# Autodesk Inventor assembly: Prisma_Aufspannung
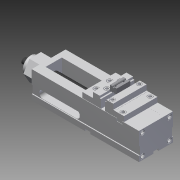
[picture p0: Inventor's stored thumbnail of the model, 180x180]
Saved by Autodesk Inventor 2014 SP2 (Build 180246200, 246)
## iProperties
Created: 2015-06
Part Number: Prisma_Aufspannung
Document SubType Name: Assembly
Designer: e_krauts
Author: e_krauts
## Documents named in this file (4)
- C:\SolidCAM_Temp\PRISMA_AUFSPANNUNG-3\DesignModel.iam
- Z:\VDW-Nachwuchsstiftung Intern\Mitarbeiter Ablage\Steffen Krauth\IVCAM\Prisma mit Passfedernut.ipt
- C:\SolidCAM_Temp\PRISMA_AUFSPANNUNG-3\Schraubstock.iam
- C:\SolidCAM_Temp\PRISMA_AUFSPANNUNG-3\Prisma mit Passfedernut-01.ipt
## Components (3 placed, 2 different names)
1. Prisma mit Passfedernut-01:1 — Passend:1, Passend:2, Fluchtend:1, Passend:3, Passend:4, Passend:5, Fluchtend:2, Passend:6
2. Schraubstock:1 [sub-assembly] — Passend:1, Passend:2, Fluchtend:1, Passend:3
3. Schraubstock:2 [sub-assembly] — Passend:4, Passend:5, Fluchtend:2, Passend:6
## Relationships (8: Mate 6, Flush 2)
- Passend:1 [Mate]: Prisma mit Passfedernut-01:1 ↔ Schraubstock:1
- Passend:2 [Mate]: Prisma mit Passfedernut-01:1 ↔ Schraubstock:1
- Fluchtend:1 [Flush]: Prisma mit Passfedernut-01:1 ↔ Schraubstock:1
- Passend:3 [Mate]: Prisma mit Passfedernut-01:1 ↔ Schraubstock:1
- Passend:4 [Mate]: Prisma mit Passfedernut-01:1 ↔ Schraubstock:2
- Passend:5 [Mate]: Prisma mit Passfedernut-01:1 ↔ Schraubstock:2
- Fluchtend:2 [Flush]: Prisma mit Passfedernut-01:1 ↔ Schraubstock:2
- Passend:6 [Mate]: Prisma mit Passfedernut-01:1 ↔ Schraubstock:2
